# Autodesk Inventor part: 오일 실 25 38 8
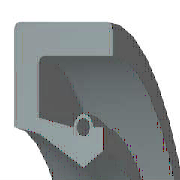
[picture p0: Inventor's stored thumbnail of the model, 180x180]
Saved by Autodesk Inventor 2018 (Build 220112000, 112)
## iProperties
IsCustomPart: 1
Created: 2012-02
Part Number: 오일 실 25 38 8
Material: 고무
Description: 오일-실
Document SubType Name: Modeling
Standard: KS B 2804
Designer: mduedu
Standards Organization: KS
Language: ko-KR
Size Designation: S - 25 38 8
Categories: <MemberInstance><Categories><Category DisplayName="샤프트 부품" InternalName="7f7aeb1f-a693-4053-b835-cee3144e0d98" Mnemonic="SHFT"><Category DisplayName="실링" Intern
Density: 0.93 g/cm^3
Appearance: 고무 - 검은색 - 버전 1.1
Author: mduedu
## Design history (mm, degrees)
revolve "본체" stored, may be unused: angle "d17" = 90 deg
revolve "스프링1" stored, may be unused: angle "d18" = 90 deg
body "Solid1"
sketch "스케치1"
  geometry: L1 (0, 19)-(8, 19); L2 (8, 19)-(8, 17.75); L3 (8, 17.75)-(1.75, 17.75); L4 (0, 19)-(0, 14.6); L5 (0, 14.6)-(1.75, 14.25); L6 (1.75, 14.25)-(4.9, 12.5); L7 (4.9, 12.5)-(0, 12.5); L8 (6.3, 13.375)-(6.3, 14.6); L9 (0, 0)-(9.586, 0) reference; L10 (4.9, 12.5)-(6.3, 13.375); L11 (0, 18)-(0, -3) reference; L12 (-1.917, 0)-(11.503, 0) reference; L13 (4.2, 14.6)-(1.75, 15.09); L14 (1.75, 15.09)-(1.75, 17.75); L15 (6.3, 14.6)-(5.6, 14.6); C1 r 0.455 at (4.9, 14.6); A1 r 0.7 centre (4.9, 14.6) between (5.6, 14.6) and (4.2, 14.6)
  constraints: 26 end point, 5 horizontal alignment, 4 perpendicular, 2 centre point, 2 collinear, 2 horizontal, 2 parallel, 2 point on circle, 2 point on line, 2 vertical alignment, 1 coincident
  dimensions: "d0" = 38 diameter of L1 L9 (= SD2); "d1" = 26.75 diameter of L8.start L9 (= ABDM); "d2" = 1.25 distance of L1.end L2.end (computed from SD); "d3" = 0.91 diameter of C1 (= SPDI); "d4" = 1.4 diameter of A1 (= SPDA); "d5" = 25 diameter of L6.end L9 (= NND); "d6" = 28.5 diameter of L5.end L9 (= TKDM); "d7" = 29.2 diameter of L4.end L9 (= HLDM); "d8" = 4.9 distance from line of C1.centre L4 (= SPDST); "d9" = 6.3 distance between parallel lines of L8 L4 (= SDI); "d10" = 8 distance between parallel lines of L2 L4 (= SWDT); "d12" = 1.75 distance between parallel lines of L14 L4 (= SD)
fillet "모깎기1" dims "d11" = 0.5 (= RR)
other parameters: "SD2" = 38 [user parameter; used in 1 equation term], "SWDT" = 8 [user parameter; used in 1 equation term], "RR" = 0.5 [user parameter; used in 1 equation term], "SD" = 1.75 [user parameter; used in 2 equation terms], "NND" = 25 [user parameter; used in 1 equation term], "SPDA" = 1.4 [user parameter; used in 1 equation term], "SPDI" = 0.91 [user parameter; used in 1 equation term], "TKDM" = 28.5 [user parameter; used in 1 equation term], "HLDM" = 29.2 [user parameter; used in 1 equation term], "ABDM" = 26.75 [user parameter; used in 1 equation term], "SDI" = 6.3 [user parameter; used in 1 equation term], "SPDST" = 4.9 [user parameter; used in 1 equation term], "d13" = 0, "d14" = 0, "d15" = 0, "LAB" = 0.35 [user parameter]
